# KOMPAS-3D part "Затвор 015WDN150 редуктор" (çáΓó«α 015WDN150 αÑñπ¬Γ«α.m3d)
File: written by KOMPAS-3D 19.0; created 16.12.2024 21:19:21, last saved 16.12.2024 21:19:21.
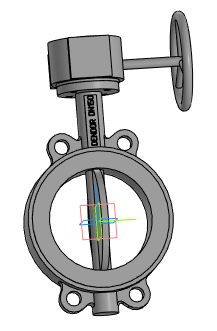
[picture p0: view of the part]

Document properties: Автор: Евгений; Полное имя файла: ..\Затвор 015WDN150 редуктор.a3d

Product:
- Part/product: Затвор 015WDN150 редуктор
    Масса: 17.863

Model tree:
1. Операция без истории:1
